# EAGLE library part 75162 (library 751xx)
75xxx DEVICE
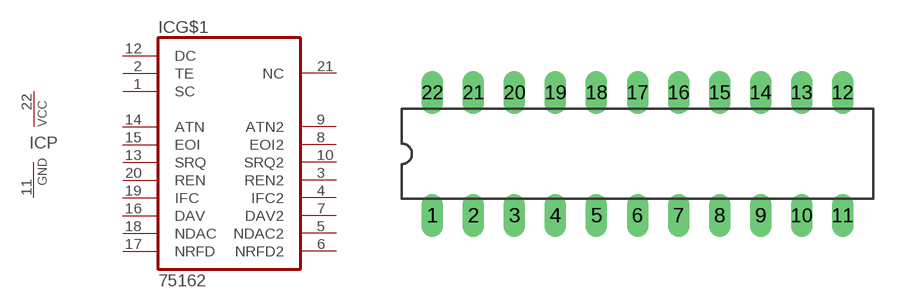
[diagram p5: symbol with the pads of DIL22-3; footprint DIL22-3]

Designator prefix IC; gates G$1=75162 P=PWRN

## 75162P  [DIL22-3]
1  G$1:SC  in
2  G$1:TE  in
3  G$1:REN2
4  G$1:IFC2
5  G$1:NDAC2
6  G$1:NRFD2
7  G$1:DAV2
8  G$1:EOI2
9  G$1:ATN2
10  G$1:SRQ2
11  P:GND  pwr
12  G$1:DC  in
13  G$1:SRQ
14  G$1:ATN
15  G$1:EOI
16  G$1:DAV
17  G$1:NRFD
18  G$1:NDAC
19  G$1:IFC
20  G$1:REN
21  G$1:NC  nc
22  P:VCC  pwr

## Footprint DIL22-3 (pad centres in mm)
Dual In Line Package 0.3 inch
drill 0.813 long: 1 -12.7,-3.81; 2 -10.16,-3.81; 3 -7.62,-3.81; 4 -5.08,-3.81; 5 -2.54,-3.81; 6 0,-3.81; 7 2.54,-3.81; 8 5.08,-3.81; 9 7.62,-3.81; 10 10.16,-3.81; 11 12.7,-3.81; 12 12.7,3.81; 13 10.16,3.81; 14 7.62,3.81; 15 5.08,3.81; 16 2.54,3.81; 17 0,3.81; 18 -2.54,3.81; 19 -5.08,3.81; 20 -7.62,3.81; 21 -10.16,3.81; 22 -12.7,3.81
